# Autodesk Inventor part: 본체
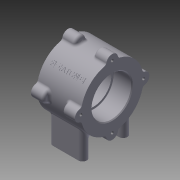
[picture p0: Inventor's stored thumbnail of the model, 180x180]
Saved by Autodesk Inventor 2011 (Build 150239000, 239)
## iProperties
Created: 2015-03
Part Number: 본체
Document SubType Name: Modeling
Designer: Administrator
Density: 2.71 g/cm^3
Material: 알루미늄-6061
Mass: 451.257 g
Surface Area: 331.783 cm^2
Volume: 166.515 cm^3
Author: Administrator
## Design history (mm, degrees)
sketch "스케치1"
  geometry: L1 (-26, 0)-(26, 0); L2 (-26, 0)-(-26, 37); L3 (26, 37)-(26, 0); L4 (26, 37)-(-26, 37); 2 further points
  constraints: 8 end point, 1 coincident, 1 midpoint
  dimensions: "d0" = 52 distance of L1.start L1.end; "d1" = 37 distance of L1.start L2.end
revolve "회전1" sketch "스케치1" stored, may be unused: angle "d2" = 90 deg
sketch "스케치2"
  geometry: L1 (0, 0)-(0, -56) reference; L2 (-29, -56)-(-29, 0); L3 (29, -56)-(29, 0); L4 (-29, -56)-(-19, -56); L5 (-19, -56)-(-19, 0.23); L6 (-19, 0.23)-(-29, 0); L7 (29, -56)-(19, -56); L8 (19, -56)-(19, -0.46); L9 (19, -0.46)-(29, 0); 1 further point
  constraints: 18 end point, 1 vertical, 1 vertical alignment
  dimensions: "d3" = 58 distance of L2.start L3.start; "d4" = 10 distance between parallel lines of L5 L2; "d5" = 10 distance between parallel lines of L3 L8; "d6" = 56 distance of L2.start L2.end; "d48" = 29 distance between parallel lines of L1 L2
extrude "돌출1" join sketch "스케치2" stored distance "d7" = 40; taper "d8" = 0 deg
sketch "스케치3"
  geometry: C1 r 7 at (0, 37); 1 further point
  constraints: 1 centre point, 1 vertical alignment, 1 other
extrude "돌출2" join sketch "스케치3" distance "d9" = 15; taper "d10" = 0 deg
fillet "모깎기1" dims "d11" = 3
sketch "스케치4"
  geometry: C1 r 23.5 at (0, -37); A1 r 37 centre (0, -37) between (9.104, -72.863) and (35.863, -46.104) reference
  constraints: 1 centre point, 1 coincident
  dimensions: "d15" = 47 diameter of C1
extrude "돌출3" cut sketch "스케치4" distance "d16" = 22; taper "d17" = 0 deg
sketch "스케치5"
  geometry: C1 r 23.5 at (-37, 0); A1 r 37 centre (-37, 0) between (-72.862, -9.104) and (-46.104, -35.863) reference
  constraints: 1 centre point, 1 coincident
extrude "돌출4" cut sketch "스케치5" distance "d18" = 22; taper "d19" = 0 deg
sketch "스케치6"
  geometry: C1 r 23.5 at (0, 0) reference; C2 r 21 at (0, 0)
  constraints: 1 centre point, 1 coincident
  dimensions: "d20" = 42 diameter of C2
extrude "돌출5" cut sketch "스케치6" stored distance "d21" = 22; taper "d22" = 0 deg
sketch "스케치7"
  geometry: A1 r 7 centre (0, 0) between (6.889, 1.239) and (-6.889, 1.239) reference; A2 r 7 centre (-37, -37) between (-38.239, -30.111) and (-38.239, -43.889) reference; A3 r 7 centre (0, -74) between (-6.889, -75.239) and (6.889, -75.239) reference; A4 r 7 centre (37, -37) between (38.239, -43.889) and (38.239, -30.111) reference
hole "Hole1" sketch "스케치7" at (-37, -37), (0, 0), (0, -74), (37, -37) diameter "d23" = 3.242; stored, may be unused: countersink angle "d27" = 90 deg, drill point angle "d29" = 118 deg; dims "d24" = 8, "d25" = 4, "d26" = 2, "d28" = 11
fillet "모깎기3" dims "d31" = 5
fillet "모깎기4" dims "d32" = 3, "d46" = 0.3
sketch "스케치8"
  geometry: A1 r 5 centre (30, -5) between (30, -10) and (30, 0) reference; A2 r 5 centre (0, -5) between (0, 0) and (0, -10) reference; 1 further point
hole "Hole2" sketch "스케치8" at (0, -5), (30, -5) diameter "d33" = 3.242; stored, may be unused: countersink angle "d37" = 90 deg, drill point angle "d39" = 118 deg; dims "d34" = 6, "d35" = 4, "d36" = 2, "d38" = 8
sketch "스케치9"
  geometry: L1 (0, 0)-(-26.163, 26.163); L2 (0, 0)-(-47.055, 0) reference; 2 further points
  constraints: 4 end point, 1 coincident, 1 horizontal
  dimensions: "d40" = 45 deg angle of L1 L2
node "작업 평면2"
sketch "스케치10"
  geometry: 2 further points
  constraints: 2 coincident, 1 other
feature "엠보싱1" sketch "스케치10" dims "d41" = 0.5, "d42" = 0
chamfer "모따기1" distance "d43" = 1; stored, may be unused: second distance "d44" = 2, angle "d45" = 45 deg
node "스케치11"
node "솔리드1"
pattern_circular "원형 패턴1" dims angle "d13" = 360 deg
mirror "대칭1"
mirror "대칭2"
mirror "대칭3"
